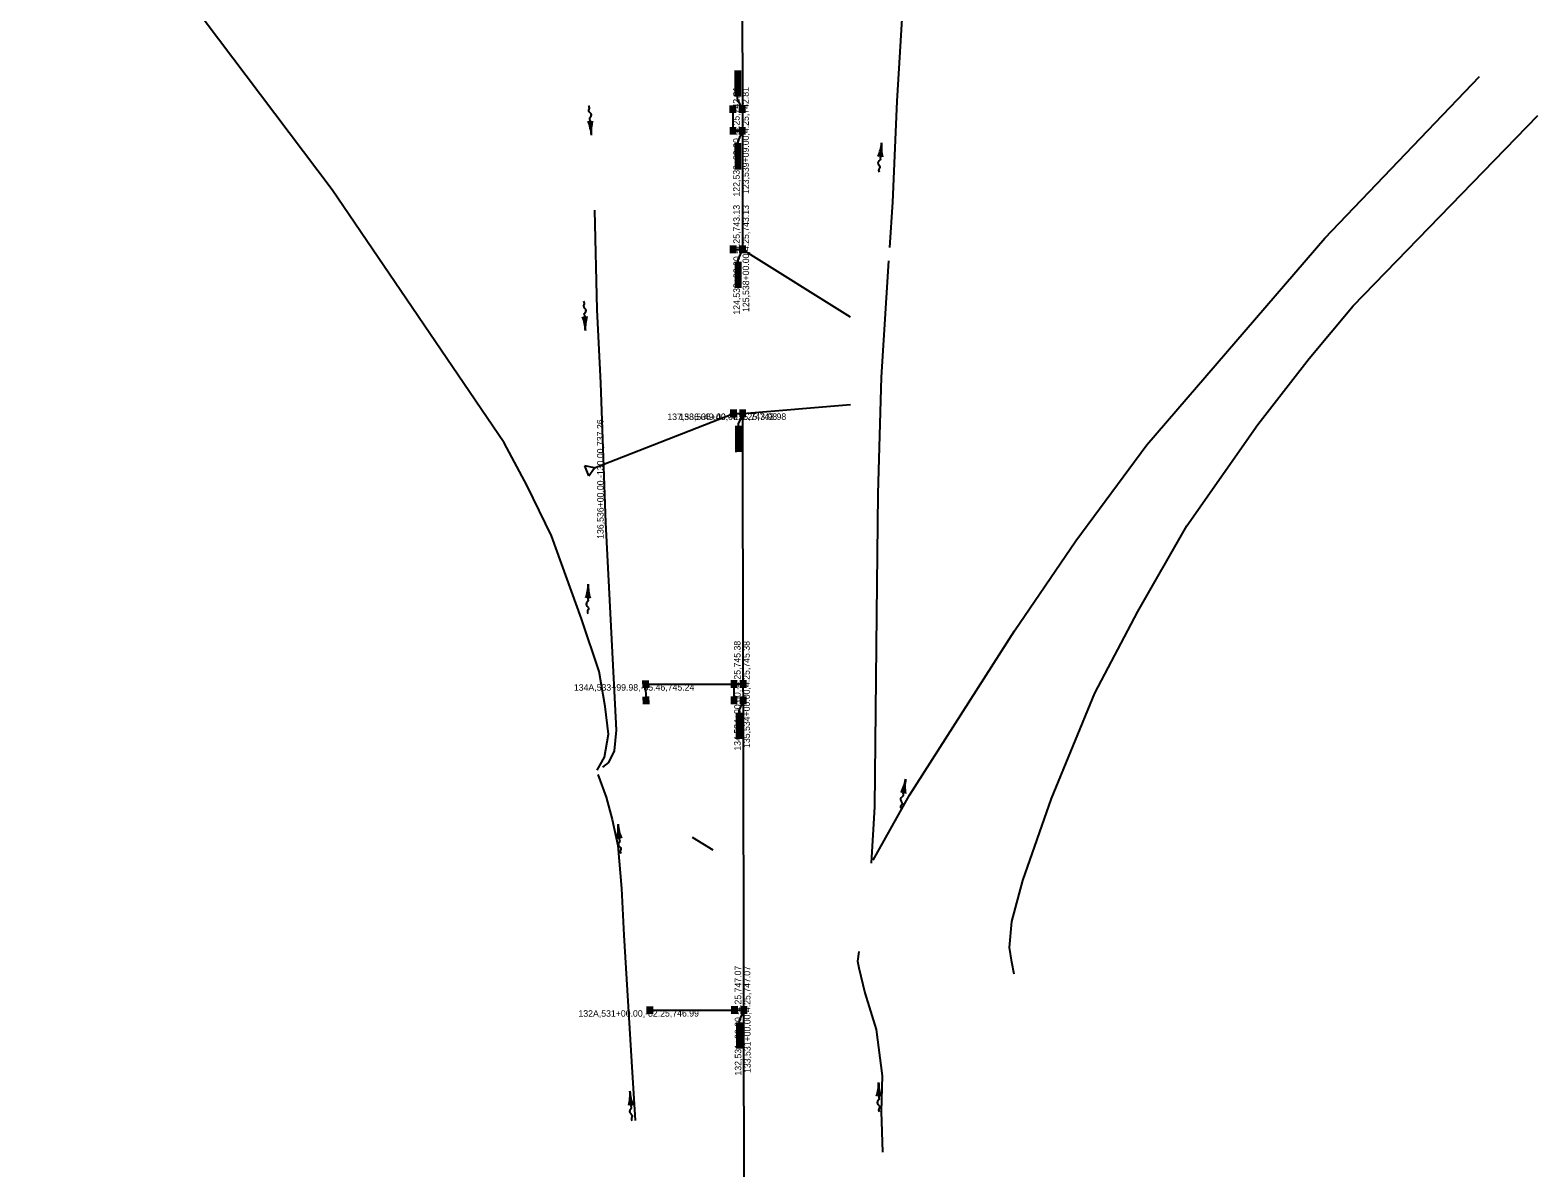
# Model space of a CAD drawing. Extents: x 593481 to 595602, y 151646 to 157396.
# Drawn here: x 593709 to 595097, y 152230 to 153277 of the extents above; entities that cross this region are included whole.
import ezdxf

# ---------------------------------------------------------------- set-up
doc = ezdxf.new("R2010")
doc.units = 0
for name, color, linetype in [('P_ALI_50_Equation', 7, 'Continuous'), ('P_DRN_Flow', 7, 'Continuous'), ('P_DRN_Inlet', 7, 'Continuous'), ('P_DRN_SS', 7, 'Continuous'), ('P_DRN_SS_UG', 7, 'Continuous')]:
    doc.layers.add(name, color=color, linetype=linetype)

msp = doc.modelspace()

# ---------------------------------------------------------------- linework, layer by layer
at = {"layer": 'P_DRN_Flow'}
for p, q in [((594225.9, 153180.4), (594224.8, 153194.5)), ((594492.9, 153173.3), (594491.6, 153159.2)), ((594220.4, 153000.5), (594219.8, 153014.6)), ((594222.9, 152767.2), (594222.7, 152753.1)), ((594515, 152587.6), (594512.6, 152573.7)), ((594250.4, 152546.1), (594251.6, 152532)), ((594261.4, 152300.5), (594262.3, 152286.4)), ((594490.2, 152308.6), (594490.3, 152294.5))]:
    msp.add_line(p, q, dxfattribs=at)
for points in [[(594222.9, 153193), (594225.1, 153190), (594226.9, 153193.3)], [(594493.7, 153160.3), (594492, 153163.7), (594489.7, 153160.7)], [(594217.8, 153013.2), (594219.9, 153010), (594221.8, 153013.3)], [(594224.8, 152754.4), (594222.8, 152757.6), (594220.8, 152754.4)], [(594514.8, 152574.6), (594513.4, 152578.1), (594510.9, 152575.3)], [(594253.5, 152533.5), (594251.2, 152536.5), (594249.5, 152533.1)], [(594492.3, 152295.8), (594490.3, 152299), (594488.3, 152295.8)], [(594264.2, 152287.8), (594262, 152290.9), (594260.2, 152287.6)]]:
    msp.add_lwpolyline(points, dxfattribs=at)
for centre, start, end in [((594184.1, 153177), 4.6994, 22.4617), ((594267.7, 153183.8), 166.9371, 184.6994), ((594451.1, 153177.2), 336.8059, 354.5682), ((594534.7, 153169.3), 174.5682, 192.3305), ((594178.4, 152998.7), 2.4314, 20.1937), ((594262.3, 153002.2), 164.6691, 182.4314), ((594181, 152767.8), 341.4611, 359.2234), ((594264.9, 152766.6), 179.2234, 196.9857), ((594473.7, 152594.8), 332.2954, 350.0578), ((594556.4, 152580.3), 170.0578, 187.8201), ((594208.6, 152542.3), 347.3129, 5.0752), ((594292.2, 152549.8), 185.0752, 202.8376), ((594219.5, 152297.9), 345.7579, 3.5203), ((594303.3, 152303), 183.5203, 201.2826), ((594448.2, 152308.3), 342.6828, 0.4452), ((594532.2, 152308.9), 180.4452, 198.2075)]:
    msp.add_arc(centre, 42, start, end, dxfattribs=at)
for points in [[(594224.8, 153194.5), (594224.4, 153195.2), (594226, 153199), (594223.5, 153202.7), (594224.2, 153205.6), (594223.4, 153207.3)], [(594491.6, 153159.2), (594491.8, 153158.4), (594489.6, 153155), (594491.4, 153150.8), (594490.2, 153148.1), (594490.7, 153146.3)], [(594219.8, 153014.6), (594219.4, 153015.3), (594221.1, 153019), (594218.8, 153022.9), (594219.6, 153025.7), (594218.9, 153027.4)], [(594222.7, 152753.1), (594223, 152752.3), (594221.1, 152748.7), (594223.3, 152744.8), (594222.3, 152741.9), (594222.9, 152740.2)], [(594512.6, 152573.7), (594512.8, 152572.8), (594510.3, 152569.6), (594511.8, 152565.4), (594510.4, 152562.8), (594510.7, 152560.9)], [(594251.6, 152532), (594252, 152531.2), (594250.5, 152527.5), (594253, 152523.8), (594252.3, 152520.9), (594253.1, 152519.2)], [(594262.3, 152286.4), (594262.6, 152285.6), (594261, 152281.9), (594263.4, 152278.1), (594262.7, 152275.2), (594263.4, 152273.5)], [(594490.3, 152294.5), (594490.6, 152293.7), (594488.8, 152290.1), (594491, 152286.2), (594490.1, 152283.3), (594490.7, 152281.6)]]:
    msp.add_spline(points, degree=3, dxfattribs=at)
at = {"layer": 'P_DRN_Inlet'}
for p, q in [((594358.2, 153239.8), (594358.2, 153215.8)), ((594359.1, 153239.8), (594359.1, 153215.8)), ((594360, 153239.8), (594360, 153215.8)), ((594360.9, 153239.8), (594360.9, 153215.8)), ((594361.8, 153239.8), (594361.8, 153215.8)), ((594362.7, 153239.8), (594362.7, 153215.8)), ((594354, 153200.8), (594354, 153207.7)), ((594354.9, 153200.8), (594354.9, 153207.7)), ((594355.8, 153200.8), (594355.8, 153207.7)), ((594356.7, 153200.8), (594356.7, 153207.7)), ((594357.6, 153200.8), (594357.6, 153207.7)), ((594358.5, 153200.8), (594358.5, 153207.7)), ((594362.5, 153200.8), (594362.5, 153207.7)), ((594363.4, 153200.8), (594363.4, 153207.7)), ((594364.3, 153200.8), (594364.3, 153207.7)), ((594365.2, 153200.8), (594365.2, 153207.7)), ((594366.1, 153200.8), (594366.1, 153207.7)), ((594367, 153200.8), (594367, 153207.7)), ((594354.1, 153180.8), (594354.1, 153187.7)), ((594355, 153180.8), (594355, 153187.7)), ((594355.9, 153180.8), (594355.9, 153187.7)), ((594356.8, 153180.8), (594356.8, 153187.7)), ((594357.7, 153180.8), (594357.7, 153187.7)), ((594358.6, 153180.8), (594358.6, 153187.7)), ((594362.6, 153180.8), (594362.6, 153187.7)), ((594363.5, 153180.8), (594363.5, 153187.7)), ((594364.4, 153180.8), (594364.4, 153187.7)), ((594365.3, 153180.8), (594365.3, 153187.7)), ((594366.2, 153180.8), (594366.2, 153187.7)), ((594367.1, 153180.8), (594367.1, 153187.7)), ((594358.3, 153172.8), (594358.4, 153148.8)), ((594359.2, 153172.8), (594359.3, 153148.8)), ((594360.1, 153172.8), (594360.2, 153148.8)), ((594361, 153172.8), (594361.1, 153148.8)), ((594361.9, 153172.8), (594362, 153148.8)), ((594362.8, 153172.8), (594362.9, 153148.8)), ((594354.3, 153071.8), (594354.3, 153078.7)), ((594355.2, 153071.8), (594355.2, 153078.7)), ((594356.1, 153071.8), (594356.1, 153078.7)), ((594357, 153071.8), (594357, 153078.7)), ((594357.9, 153071.8), (594357.9, 153078.7)), ((594358.8, 153071.8), (594358.8, 153078.7)), ((594362.8, 153071.8), (594362.8, 153078.7)), ((594363.7, 153071.8), (594363.7, 153078.7)), ((594364.6, 153071.8), (594364.6, 153078.7)), ((594365.5, 153071.8), (594365.5, 153078.7)), ((594366.4, 153071.8), (594366.4, 153078.7)), ((594367.3, 153071.8), (594367.3, 153078.7)), ((594358.5, 153063.8), (594358.6, 153039.8)), ((594359.4, 153063.8), (594359.5, 153039.8)), ((594360.3, 153063.8), (594360.4, 153039.8)), ((594361.2, 153063.8), (594361.3, 153039.8)), ((594362.1, 153063.8), (594362.2, 153039.8)), ((594363, 153063.8), (594363.1, 153039.8)), ((594354.5, 152920.8), (594354.5, 152927.7)), ((594355.4, 152920.8), (594355.4, 152927.7)), ((594356.3, 152920.8), (594356.3, 152927.7)), ((594357.2, 152920.8), (594357.2, 152927.7)), ((594358.1, 152920.8), (594358.1, 152927.7)), ((594359, 152920.8), (594359, 152927.7)), ((594363, 152920.8), (594363, 152927.7)), ((594363.9, 152920.8), (594363.9, 152927.7)), ((594364.8, 152920.8), (594364.8, 152927.7)), ((594365.7, 152920.8), (594365.7, 152927.7)), ((594366.6, 152920.8), (594366.6, 152927.7)), ((594367.5, 152920.8), (594367.5, 152927.7)), ((594358.8, 152912.7), (594358.8, 152888.7)), ((594359.7, 152912.8), (594359.7, 152888.8)), ((594360.6, 152912.8), (594360.6, 152888.8)), ((594361.5, 152912.8), (594361.5, 152888.8)), ((594362.4, 152912.8), (594362.4, 152888.8)), ((594363.3, 152912.8), (594363.3, 152888.8)), ((594273.8, 152671.6), (594273.7, 152678.5)), ((594274.7, 152671.6), (594274.6, 152678.5)), ((594275.6, 152671.6), (594275.5, 152678.5)), ((594276.5, 152671.6), (594276.4, 152678.5)), ((594277.4, 152671.7), (594277.3, 152678.5)), ((594278.3, 152671.7), (594278.2, 152678.6)), ((594355, 152671.8), (594355, 152678.7)), ((594355.9, 152671.8), (594355.9, 152678.7)), ((594356.8, 152671.8), (594356.8, 152678.7)), ((594357.7, 152671.8), (594357.7, 152678.7)), ((594358.6, 152671.8), (594358.6, 152678.7)), ((594359.5, 152671.8), (594359.5, 152678.7)), ((594363.5, 152671.8), (594363.5, 152678.7)), ((594364.4, 152671.8), (594364.4, 152678.7)), ((594365.3, 152671.8), (594365.3, 152678.7)), ((594366.2, 152671.8), (594366.2, 152678.7)), ((594367.1, 152671.8), (594367.1, 152678.7)), ((594368, 152671.8), (594368, 152678.7)), ((594274.2, 152656.6), (594274, 152663.5)), ((594275.1, 152656.6), (594274.9, 152663.5)), ((594276, 152656.6), (594275.8, 152663.5)), ((594276.9, 152656.7), (594276.7, 152663.5)), ((594277.8, 152656.7), (594277.6, 152663.6)), ((594278.7, 152656.7), (594278.5, 152663.6)), ((594355, 152656.8), (594355, 152663.7)), ((594355.9, 152656.8), (594355.9, 152663.7)), ((594356.8, 152656.8), (594356.8, 152663.7)), ((594357.7, 152656.8), (594357.7, 152663.7)), ((594358.6, 152656.8), (594358.6, 152663.7)), ((594359.5, 152656.8), (594359.5, 152663.7)), ((594363.5, 152656.8), (594363.5, 152663.7)), ((594364.4, 152656.8), (594364.4, 152663.7)), ((594365.3, 152656.8), (594365.3, 152663.7)), ((594366.2, 152656.8), (594366.2, 152663.7)), ((594367.1, 152656.8), (594367.1, 152663.7)), ((594368, 152656.8), (594368, 152663.7)), ((594359.3, 152648.7), (594359.3, 152624.7)), ((594360.2, 152648.7), (594360.2, 152624.7)), ((594361.1, 152648.7), (594361.1, 152624.7)), ((594362, 152648.7), (594362, 152624.7)), ((594362.9, 152648.7), (594362.9, 152624.7)), ((594363.8, 152648.7), (594363.8, 152624.7)), ((594277.5, 152371.7), (594277.5, 152378.5)), ((594278.4, 152371.7), (594278.4, 152378.5)), ((594279.3, 152371.7), (594279.3, 152378.5)), ((594280.2, 152371.7), (594280.2, 152378.5)), ((594281.1, 152371.7), (594281.1, 152378.5)), ((594282, 152371.7), (594282, 152378.5)), ((594355.5, 152371.8), (594355.5, 152378.7)), ((594356.4, 152371.8), (594356.4, 152378.7)), ((594357.3, 152371.8), (594357.3, 152378.7)), ((594358.2, 152371.8), (594358.2, 152378.7)), ((594359.1, 152371.8), (594359.1, 152378.7)), ((594360, 152371.8), (594360, 152378.7)), ((594364, 152371.8), (594364, 152378.7)), ((594364.9, 152371.8), (594364.9, 152378.7)), ((594365.8, 152371.8), (594365.8, 152378.7)), ((594366.7, 152371.8), (594366.7, 152378.7)), ((594367.6, 152371.8), (594367.6, 152378.7)), ((594368.5, 152371.8), (594368.5, 152378.7)), ((594359.8, 152363.7), (594359.8, 152339.7)), ((594360.7, 152363.7), (594360.7, 152339.7)), ((594361.6, 152363.7), (594361.6, 152339.7)), ((594362.5, 152363.7), (594362.5, 152339.7)), ((594363.4, 152363.7), (594363.4, 152339.7)), ((594364.3, 152363.7), (594364.3, 152339.7))]:
    msp.add_line(p, q, dxfattribs=at)
for points in [[(594359.5, 153235), (594359.5, 153220.5), (594361.5, 153220.5), (594361.5, 153235)], [(594357.3, 153203.2), (594357.3, 153205.2), (594355.3, 153205.2), (594355.3, 153203.2)], [(594365.8, 153203.3), (594365.8, 153205.3), (594363.8, 153205.3), (594363.8, 153203.3)], [(594357.3, 153183.2), (594357.3, 153185.2), (594355.3, 153185.2), (594355.3, 153183.2)], [(594365.8, 153183.3), (594365.8, 153185.3), (594363.8, 153185.2), (594363.8, 153183.2)], [(594359.6, 153168), (594359.6, 153153.5), (594361.6, 153153.5), (594361.6, 153168)], [(594357.5, 153074.2), (594357.5, 153076.2), (594355.5, 153076.2), (594355.5, 153074.2)], [(594366, 153074.3), (594366, 153076.3), (594364, 153076.2), (594364, 153074.2)], [(594359.8, 153059), (594359.8, 153044.5), (594361.8, 153044.5), (594361.8, 153059)], [(594357.8, 152923.2), (594357.8, 152925.2), (594355.8, 152925.2), (594355.8, 152923.2)], [(594366.3, 152923.3), (594366.3, 152925.3), (594364.3, 152925.2), (594364.3, 152923.2)], [(594360, 152908), (594360.1, 152893.5), (594362.1, 152893.5), (594362, 152908)], [(594277, 152674.1), (594277, 152676.1), (594275, 152676), (594275, 152674)], [(594358.2, 152674.2), (594358.2, 152676.2), (594356.2, 152676.2), (594356.2, 152674.2)], [(594366.7, 152674.3), (594366.7, 152676.3), (594364.7, 152676.2), (594364.7, 152674.2)], [(594277.4, 152659.1), (594277.3, 152661.1), (594275.3, 152661.1), (594275.4, 152659.1)], [(594358.3, 152659.2), (594358.3, 152661.2), (594356.3, 152661.2), (594356.3, 152659.2)], [(594366.8, 152659.3), (594366.8, 152661.3), (594364.8, 152661.3), (594364.8, 152659.3)], [(594360.5, 152644), (594360.6, 152629.5), (594362.6, 152629.5), (594362.5, 152644)], [(594280.8, 152374.1), (594280.8, 152376.1), (594278.8, 152376.1), (594278.8, 152374.1)], [(594358.8, 152374.2), (594358.8, 152376.2), (594356.8, 152376.2), (594356.8, 152374.2)], [(594367.3, 152374.3), (594367.3, 152376.3), (594365.3, 152376.2), (594365.3, 152374.2)], [(594361, 152359), (594361.1, 152344.4), (594363.1, 152344.4), (594363, 152359)]]:
    msp.add_lwpolyline(points, close=True, dxfattribs=at)
at = {"layer": 'P_DRN_SS'}
for p, q in [((594228.7, 152874.1), (594219.9, 152876)), ((594223.6, 152866.7), (594219.9, 152876)), ((594223.6, 152866.7), (594228.7, 152874.1))]:
    msp.add_line(p, q, dxfattribs=at)
at = {"layer": 'P_DRN_SS_UG'}
for p, q in [((594364.3, 153455.3), (594364.8, 153204.3)), ((594356.3, 153184.2), (594356.3, 153204.2)), ((594364.8, 153204.3), (594364.8, 153184.2)), ((594356.3, 153184.2), (594364.8, 153184.2)), ((594364.8, 153184.2), (594365, 153075.2)), ((594356.5, 153075.2), (594365, 153075.2)), ((594365, 153075.2), (594463.9, 153013.1)), ((594228.7, 152874.1), (594356.8, 152924.2)), ((594356.8, 152924.2), (594365.3, 152924.3)), ((594365.3, 152924.3), (594464.3, 152932.3)), ((594365.7, 152675.3), (594365.3, 152924.3)), ((594276, 152675.1), (594357.2, 152675.2)), ((594276.3, 152660.1), (594276, 152675.1)), ((594357.2, 152675.2), (594365.7, 152675.3)), ((594357.3, 152660.2), (594357.2, 152675.2)), ((594365.8, 152660.3), (594365.7, 152675.3)), ((594366.3, 152375.3), (594365.8, 152660.3)), ((594337.9, 152522.4), (594318.8, 152534.1)), ((594279.8, 152375.1), (594357.8, 152375.2)), ((594357.8, 152375.2), (594366.3, 152375.3)), ((594366.8, 152075.3), (594366.3, 152375.3))]:
    msp.add_line(p, q, dxfattribs=at)
for points in [[(594577.5, 153627.4), (594576.8, 153554.4), (594573.6, 153518.6), (594565.2, 153492.1), (594557, 153474.1), (594550.3, 153464.5), (594536.3, 153453.1), (594527.8, 153443.5), (594521.5, 153427.4), (594519.3, 153413.7), (594507, 153211.5), (594503.1, 153118.7), (594500.3, 153076.8)], [(594231.3, 152595.8), (594238, 152608), (594241.5, 152629.1), (594238.7, 152654.6), (594233.1, 152686.7), (594216.9, 152735.1), (594189.3, 152811.5), (594166.9, 152857.5), (594145.5, 152897.2), (593987.3, 153130.1), (593816.8, 153356.3), (593736.8, 153457), (593709.5, 153500.1)], [(594485.1, 152513), (594518.7, 152572.8), (594615.2, 152724.2), (594671.6, 152807), (594737, 152895.2), (594900.9, 153085.6), (595043.1, 153234.2)], [(594364.8, 153204.3), (594360.5, 153213.8), (594360.5, 153215.8)], [(594615, 152408.3), (594612.8, 152419.1), (594610.7, 152432.6), (594612.9, 152456.8), (594622.9, 152494.3), (594649.2, 152569.9), (594689.2, 152666.7), (594728.7, 152741.9), (594773.9, 152820.7), (594839.1, 152914.1), (594886.3, 152974.9), (594926.7, 153023.2), (595096.8, 153198.4)], [(594364.8, 153184.2), (594360.6, 153174.8), (594360.6, 153172.8)], [(594236.5, 152598.7), (594241.9, 152603), (594247.3, 152613.7), (594249, 152632.8), (594239.2, 152824), (594234.7, 152952), (594231.2, 153020), (594229, 153111.2)], [(594365, 153075.2), (594360.8, 153065.8), (594360.8, 153063.8)], [(594483.6, 152510.2), (594486.8, 152562.1), (594488.7, 152739.3), (594489.9, 152850.1), (594492.7, 152957.6), (594499.6, 153064.8)], [(594365.3, 152924.3), (594361, 152914.8), (594361.1, 152912.8)], [(594365.8, 152660.3), (594361.5, 152650.7), (594361.5, 152648.7)], [(594231.7, 152592), (594239.5, 152571.2), (594244.9, 152550.4), (594250.2, 152526.5), (594253.7, 152487.1), (594255.7, 152444), (594262.9, 152327.7), (594266.1, 152273.5)], [(594472, 152429.1), (594470.8, 152420.2), (594472.1, 152414), (594477.6, 152391), (594487.9, 152357.3), (594493.5, 152314.7), (594492.6, 152281.8), (594493.7, 152244.4)], [(594366.3, 152375.3), (594362, 152365.7), (594362, 152363.7)]]:
    msp.add_lwpolyline(points, dxfattribs=at)

# ---------------------------------------------------------------- texts
at = {"layer": 'P_ALI_50_Equation'}
for s, rotation, p in [('122,539+09.00,-4.25,742.81', 90.103, (594362.4, 153123.8)), ('123,539+09.00,4.25,742.81', 90.103, (594370.9, 153126.2)), ('124,538+00.00,-4.25,743.13', 90.103, (594362.6, 153015.1)), ('125,538+00.00,4.25,743.13', 90.103, (594371.1, 153017.6)), ('137,536+49.00,-4.25,743.98', 0.103, (594295.8, 152918.1)), ('138,536+49.00,4.25,743.98', 0.103, (594306.8, 152918.1)), ('136,536+00.00,-130.00,737.26', 90.103, (594237.2, 152808.8)), ('134,534+00.00,-4.25,745.38', 90.103, (594363.3, 152613.9)), ('135,534+00.00,4.25,745.38', 90.103, (594371.8, 152616.4)), ('134A,533+99.98,-85.46,745.24', 0.103, (594209.8, 152669)), ('132,531+00.00,-4.25,747.07', 90.103, (594363.9, 152314.9)), ('133,531+00.00,4.25,747.07', 90.103, (594372.4, 152317.3)), ('132A,531+00.00,-82.25,746.99', 0.103, (594214, 152369))]:
    msp.add_text(s, height=6, rotation=rotation, dxfattribs=at).set_placement(p)

doc.saveas('drawing.dxf')
